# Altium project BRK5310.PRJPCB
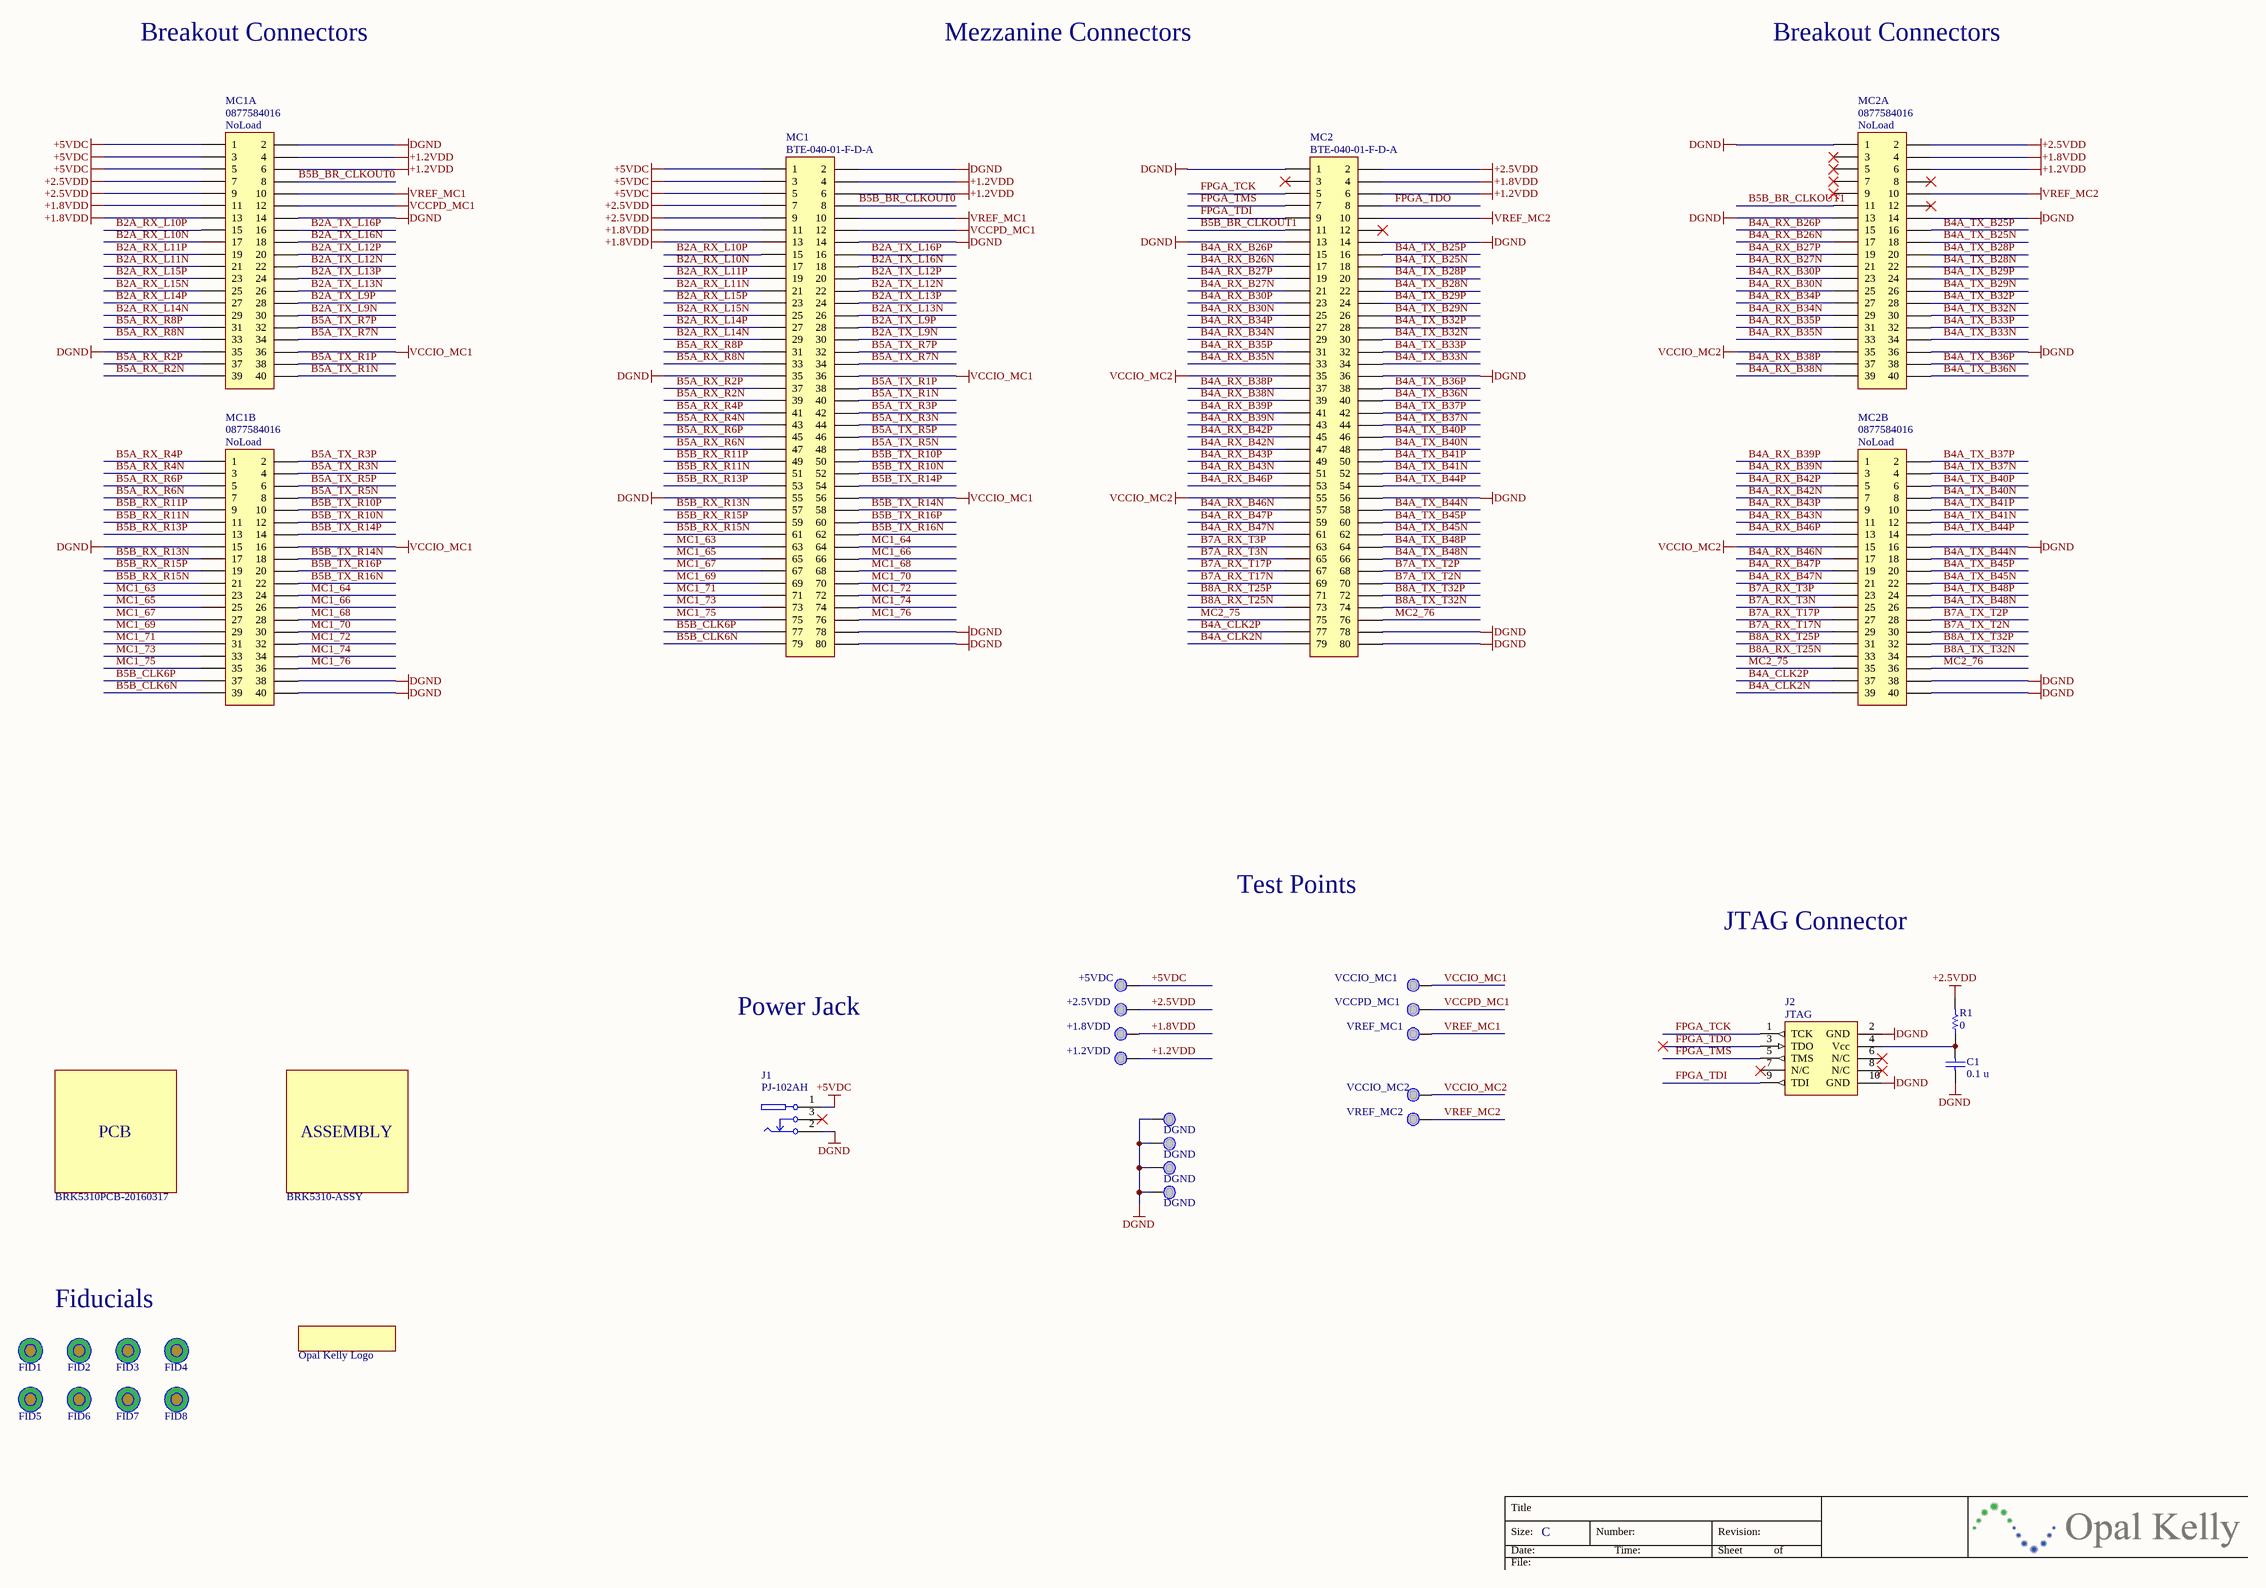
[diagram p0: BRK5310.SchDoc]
1 sheet, 34 parts. Net scope: global (net labels, ports and power ports of the same name join across sheets).
Board file: BRK5310.PcbDoc

## Sheet BRK5310.SchDoc: BRK5310
size C; Organization: Opal Kelly; Address1: 13500 SW 72nd Ave, STE 100; Address2: Portland, OR 97223; Address4: http://www.opalkelly.com; DocumentNumber: xxx; Revision: 1; SheetNumber: 1; SheetTotal: 1; PageSetup: Record=PageOptions¦CenterHorizontal=True¦CenterVertical=True¦PrintScale=0.54¦XCorrection=1.00¦YCorrection=1.00¦PrintKind=0¦BorderSize=5000000¦LeftOffset=0¦BottomOffset=0¦Orientation=2¦PaperLength=1000¦PaperWidth=1000¦Scale=100¦PaperSource=7¦PrintQuality=-4¦MediaType=1¦DitherType=10¦PaperKind=Letter¦PrintScaleMode=1

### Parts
*  Opal Kelly Logo  [okLogo-23x5]
ASSY1  BRK5310-ASSY  (mechanical)
C1  value 0.1 u  [CAPC1608N]  (hidden comment: C0603C104K4RACTU)
FID1  FIDUCIAL  [FID1MM/2MM-SS]  (value not drawn)
FID2  FIDUCIAL  [FID1MM/2MM-SS]  (value not drawn)
FID3  FIDUCIAL  [FID1MM/2MM-SS]  (value not drawn)
FID4  FIDUCIAL  [FID1MM/2MM-SS]  (value not drawn)
FID5  FIDUCIAL  [FID1MM/2MM-SS]  (value not drawn)
FID6  FIDUCIAL  [FID1MM/2MM-SS]  (value not drawn)
FID7  FIDUCIAL  [FID1MM/2MM-SS]  (value not drawn)
FID8  FIDUCIAL  [FID1MM/2MM-SS]  (value not drawn)
J1  PJ-102AH  [CUI-PJ102A]
J2  JTAG  [HDR2X5-SHRD]
MC1  BTE-040-01-F-D-A  [BTE-040]
MC1A  0877584016  [HDR2X20-2MM]
MC1B  0877584016  [HDR2X20-2MM]
MC2  BTE-040-01-F-D-A  [BTE-040]
MC2A  0877584016  [HDR2X20-2MM]
MC2B  0877584016  [HDR2X20-2MM]
PCB1  BRK5310PCB-20160317  (mechanical)
R1  value 0  [RESC1608N]  (hidden comment: CRCW06030000Z0EA)
TP1  +5VDC  [TP_MED]
TP2  VCCIO_MC1  [TP_MED]
TP3  +2.5VDD  [TP_MED]
TP4  VCCPD_MC1  [TP_MED]
TP5  +1.2VDD  [TP_MED]
TP6  +1.8VDD  [TP_MED]
TP7  VREF_MC1  [TP_MED]
TP8  VREF_MC2  [TP_MED]
TP9  VCCIO_MC2  [TP_MED]
TP10  DGND  [TP_MED]
TP11  DGND  [TP_MED]
TP12  DGND  [TP_MED]
TP13  DGND  [TP_MED]

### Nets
+1.2VDD: MC1.4 MC1.6 MC1A.4 MC1A.6 MC2.6 MC2A.6 TP5.1(PIN)
+1.8VDD: MC1.11 MC1.13 MC1A.11 MC1A.13 MC2.4 MC2A.4 TP6.1(PIN)
+2.5VDD: MC1.7 MC1.9 MC1A.7 MC1A.9 MC2.2 MC2A.2 R1.2 TP3.1(PIN)
+5VDC: J1.1 MC1.1 MC1.3 MC1.5 MC1A.1 MC1A.3 MC1A.5 TP1.1(PIN)
DGND: C1.1 J1.2 J2.2(GND) J2.10(GND) MC1.2 MC1.14 MC1.35 MC1.55 MC1.78 MC1.80 MC1A.2 MC1A.14 MC1A.35 MC1B.15 MC1B.38 MC1B.40 MC2.1 MC2.13 MC2.14 MC2.36 MC2.56 MC2.78 MC2.80 MC2A.1 MC2A.13 MC2A.14 MC2A.36 MC2B.16 MC2B.38 MC2B.40 TP10.1(PIN) TP11.1(PIN) TP12.1(PIN) TP13.1(PIN)
VCCIO_MC1: MC1.36 MC1.56 MC1A.36 MC1B.16 TP2.1(PIN)
VCCIO_MC2: MC2.35 MC2.55 MC2A.35 MC2B.15 TP9.1(PIN)
VCCPD_MC1: MC1.12 MC1A.12 TP4.1(PIN)
VREF_MC1: MC1.10 MC1A.10 TP7.1(PIN)
VREF_MC2: MC2.10 MC2A.10 TP8.1(PIN)
B2A_RX_L10N: MC1.17 MC1A.17
B2A_RX_L10P: MC1.15 MC1A.15
B2A_RX_L11N: MC1.21 MC1A.21
B2A_RX_L11P: MC1.19 MC1A.19
B2A_RX_L14N: MC1.29 MC1A.29
B2A_RX_L14P: MC1.27 MC1A.27
B2A_RX_L15N: MC1.25 MC1A.25
B2A_RX_L15P: MC1.23 MC1A.23
B2A_TX_L9N: MC1.30 MC1A.30
B2A_TX_L9P: MC1.28 MC1A.28
B2A_TX_L12N: MC1.22 MC1A.22
B2A_TX_L12P: MC1.20 MC1A.20
B2A_TX_L13N: MC1.26 MC1A.26
B2A_TX_L13P: MC1.24 MC1A.24
B2A_TX_L16N: MC1.18 MC1A.18
B2A_TX_L16P: MC1.16 MC1A.16
B4A_CLK2N: MC2.79 MC2B.39
B4A_CLK2P: MC2.77 MC2B.37
B4A_RX_B26N: MC2.17 MC2A.17
B4A_RX_B26P: MC2.15 MC2A.15
B4A_RX_B27N: MC2.21 MC2A.21
B4A_RX_B27P: MC2.19 MC2A.19
B4A_RX_B30N: MC2.25 MC2A.25
B4A_RX_B30P: MC2.23 MC2A.23
B4A_RX_B34N: MC2.29 MC2A.29
B4A_RX_B34P: MC2.27 MC2A.27
B4A_RX_B35N: MC2.33 MC2A.33
B4A_RX_B35P: MC2.31 MC2A.31
B4A_RX_B38N: MC2.39 MC2A.39
B4A_RX_B38P: MC2.37 MC2A.37
B4A_RX_B39N: MC2.43 MC2B.3
B4A_RX_B39P: MC2.41 MC2B.1
B4A_RX_B42N: MC2.47 MC2B.7
B4A_RX_B42P: MC2.45 MC2B.5
B4A_RX_B43N: MC2.51 MC2B.11
B4A_RX_B43P: MC2.49 MC2B.9
B4A_RX_B46N: MC2.57 MC2B.17
B4A_RX_B46P: MC2.53 MC2B.13
B4A_RX_B47N: MC2.61 MC2B.21
B4A_RX_B47P: MC2.59 MC2B.19
B4A_TX_B25N: MC2.18 MC2A.18
B4A_TX_B25P: MC2.16 MC2A.16
B4A_TX_B28N: MC2.22 MC2A.22
B4A_TX_B28P: MC2.20 MC2A.20
B4A_TX_B29N: MC2.26 MC2A.26
B4A_TX_B29P: MC2.24 MC2A.24
B4A_TX_B32N: MC2.30 MC2A.30
B4A_TX_B32P: MC2.28 MC2A.28
B4A_TX_B33N: MC2.34 MC2A.34
B4A_TX_B33P: MC2.32 MC2A.32
B4A_TX_B36N: MC2.40 MC2A.40
B4A_TX_B36P: MC2.38 MC2A.38
B4A_TX_B37N: MC2.44 MC2B.4
B4A_TX_B37P: MC2.42 MC2B.2
B4A_TX_B40N: MC2.48 MC2B.8
B4A_TX_B40P: MC2.46 MC2B.6
B4A_TX_B41N: MC2.52 MC2B.12
B4A_TX_B41P: MC2.50 MC2B.10
B4A_TX_B44N: MC2.58 MC2B.18
B4A_TX_B44P: MC2.54 MC2B.14
B4A_TX_B45N: MC2.62 MC2B.22
B4A_TX_B45P: MC2.60 MC2B.20
B4A_TX_B48N: MC2.66 MC2B.26
B4A_TX_B48P: MC2.64 MC2B.24
B5A_RX_R2N: MC1.39 MC1A.39
B5A_RX_R2P: MC1.37 MC1A.37
B5A_RX_R4N: MC1.43 MC1B.3
B5A_RX_R4P: MC1.41 MC1B.1
B5A_RX_R6N: MC1.47 MC1B.7
B5A_RX_R6P: MC1.45 MC1B.5
B5A_RX_R8N: MC1.33 MC1A.33
B5A_RX_R8P: MC1.31 MC1A.31
B5A_TX_R1N: MC1.40 MC1A.40
B5A_TX_R1P: MC1.38 MC1A.38
B5A_TX_R3N: MC1.44 MC1B.4
B5A_TX_R3P: MC1.42 MC1B.2
B5A_TX_R5N: MC1.48 MC1B.8
B5A_TX_R5P: MC1.46 MC1B.6
B5A_TX_R7N: MC1.34 MC1A.34
B5A_TX_R7P: MC1.32 MC1A.32
B5B_BR_CLKOUT0: MC1.8 MC1A.8
B5B_BR_CLKOUT1: MC2.11 MC2A.11
B5B_CLK6N: MC1.79 MC1B.39
B5B_CLK6P: MC1.77 MC1B.37
B5B_RX_R11N: MC1.51 MC1B.11
B5B_RX_R11P: MC1.49 MC1B.9
B5B_RX_R13N: MC1.57 MC1B.17
B5B_RX_R13P: MC1.53 MC1B.13
B5B_RX_R15N: MC1.61 MC1B.21
B5B_RX_R15P: MC1.59 MC1B.19
B5B_TX_R10N: MC1.52 MC1B.12
B5B_TX_R10P: MC1.50 MC1B.10
B5B_TX_R14N: MC1.58 MC1B.18
B5B_TX_R14P: MC1.54 MC1B.14
B5B_TX_R16N: MC1.62 MC1B.22
B5B_TX_R16P: MC1.60 MC1B.20
B7A_RX_T3N: MC2.65 MC2B.25
B7A_RX_T3P: MC2.63 MC2B.23
B7A_RX_T17N: MC2.69 MC2B.29
B7A_RX_T17P: MC2.67 MC2B.27
B7A_TX_T2N: MC2.70 MC2B.30
B7A_TX_T2P: MC2.68 MC2B.28
B8A_RX_T25N: MC2.73 MC2B.33
B8A_RX_T25P: MC2.71 MC2B.31
B8A_TX_T32N: MC2.74 MC2B.34
B8A_TX_T32P: MC2.72 MC2B.32
FPGA_TCK: J2.1(TCK) MC2.5
FPGA_TDI: J2.9(TDI) MC2.9
FPGA_TDO: J2.3(TDO) MC2.8
FPGA_TMS: J2.5(TMS) MC2.7
MC1_63: MC1.63 MC1B.23
MC1_64: MC1.64 MC1B.24
MC1_65: MC1.65 MC1B.25
MC1_66: MC1.66 MC1B.26
MC1_67: MC1.67 MC1B.27
MC1_68: MC1.68 MC1B.28
MC1_69: MC1.69 MC1B.29
MC1_70: MC1.70 MC1B.30
MC1_71: MC1.71 MC1B.31
MC1_72: MC1.72 MC1B.32
MC1_73: MC1.73 MC1B.33
MC1_74: MC1.74 MC1B.34
MC1_75: MC1.75 MC1B.35
MC1_76: MC1.76 MC1B.36
MC2_75: MC2.75 MC2B.35
MC2_76: MC2.76 MC2B.36
NetC1_2: C1.2 J2.4(Vcc) R1.1

Not connected (* = marked no-connect by the designer): J1 3*; J2 6(N/C)* 7(N/C)* 8(N/C)*; MC2 3* 12*; MC2A 3* 5* 7* 8* 9* 12*

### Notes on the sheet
- Breakout Connectors
- Mezzanine Connectors
- Test Points
- JTAG Connector
- Power Jack
- Fiducials
- Title
- Size:
- Date:
- File:
- C
- Number:
- Time:
- Revision:
- Sheet
- of

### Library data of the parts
* = OKLOGO
ASSY1 = 001399: BRK5310 PCB assembly; Manufacturer: PCB Assembly Cost; partnumber: 001399
C1 = 000019: Ceramic capacitor; Manufacturer: Kemet; partnumber: 000019; Description 2: SM-0603, 10%, 16v, X7R; ValueFloat: 1E-7; x_lifecycle_status: Production
FID1-FID8 = FIDUCIAL: PCB fiducial
J1 = 000356: DC power connector - high current; Manufacturer: CUI Inc.; partnumber: 000356; Description 2: 2.1mm / 5.5mm
J2 = 000777: 2.54mm, 10 Pos, Dual Row Header; Manufacturer: Molex; Manufacturer_PN: 70246-1004; partnumber: 000777; Description 2: Altera JTAG Compatible
MC1 MC2 = 000059: 0.8mm high-density header; Manufacturer: Samtec; partnumber: 000059; Description 2: 80-pin, Gold flash, Mated height: 5.00mm (0.197 inch)
MC1A MC1B MC2A MC2B = 000583: 2mm header, 20x2, thru-hole; Manufacturer: Molex; partnumber: 000583
PCB1 = 001400: PCB for BRK5310; Manufacturer: Generic PCB Manufacturer; partnumber: 001400; x_lifecycle_status: Prototype
R1 = 000411: Zero-ohm resistor; Manufacturer: Vishay; partnumber: 000411; Description 2: SM-0603, 1/10W, 20 mOhm max
TP1-TP13 = 000265: Testpoint; Manufacturer: Keystone Electronics; Manufacturer_PN: 5007; partnumber: 000265; Description 2: 0.063 in. diameter, compact, White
